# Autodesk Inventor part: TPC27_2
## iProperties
Shininess: 64.0
Length Units: 11272
Angle Units: 11279
Time Units: 11290
Mass Units: 11286
Length Display Precision: 3
Angle Display Precision: 2
Compacted: True
Part Number: TPC27_2
Document SubType Name: Modeling
Created: 2004-08
Designer: Lori
Manufacturer: Standard
Standards Organization: Custom
Density: 0.0
Volumn: 0.0
Area: 0.0
PropertySet Name: Model Information
Control State: 0
Master: False
Checked Out: False
Author: Lori
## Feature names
1. Base1
